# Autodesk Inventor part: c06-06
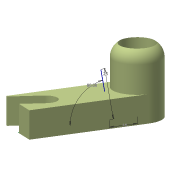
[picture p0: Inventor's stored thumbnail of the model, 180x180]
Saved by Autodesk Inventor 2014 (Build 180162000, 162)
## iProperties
Created: 2013-03
Part Number: c06-06
Material: Aluminum 6061
Document SubType Name: Modeling
Designer: Thom Tremblay
Density: 2.71 g/cm^3
Appearance: Zinc Chromate 2
Author: Thom Tremblay
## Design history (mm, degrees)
sketch "Sketch1"
  geometry: L1 (0, -12.5)-(60, -12.5); L2 (60, -12.5)-(60, 12.5); L3 (60, 12.5)-(0, 12.5); L4 (0, 12.5)-(0, -12.5); 2 further points
  constraints: 8 end point, 2 parallel, 1 coincident, 1 horizontal, 1 midpoint, 1 perpendicular
  dimensions: "d1" = 25 distance of L2.end L1.end; "d2" = 60 distance of L2.end L3.end
extrude "Base" new body sketch "Sketch1" distance "d3" = 14; taper "d4" = 0 deg
sketch "Sketch2"
  geometry: C1 r 12.5 at (0, 0); 1 further point
  constraints: 1 centre point, 1 coincident
extrude "Boss" join sketch "Sketch2" distance "d5" = 35; taper "d6" = 0 deg
sketch "Sketch3"
  geometry: L1 (-60, 12.5)-(-60, -12.5) reference; L2 (-60, -6)-(-60, 6); L3 (-43.948, 5.638)-(-60, 11.481); L4 (-48.052, -5.638)-(-60, -1.289); L5 (-60, 11.481)-(-60, -1.289); A1 r 6 centre (-46, 0) between (-43.948, 5.638) and (-48.052, -5.638); 2 further points
  constraints: 8 end point, 3 midpoint, 2 point on circle, 2 point on line, 2 tangent, 1 centre point, 1 collinear, 1 horizontal alignment, 1 parallel
  dimensions: "d8" = 12 diameter of A1; "d20" = 20 dimension on A1 L1; "d27" = 70 deg angle of L1 L3
extrude "Slot" cut sketch "Sketch3" stored distance "d9" = 24; taper "d10" = 0 deg
hole "Hole1" diameter "d13" = 11; stored, may be unused: countersink angle "d17" = 90 deg, drill point angle "d19" = 118 deg; dims "d11" = 10, "d12" = 10, "d14" = 6, "d15" = 18, "d16" = 11, "d18" = 8
fillet "Fillet1" dims "d26" = 8
node "Midplane between faces"
node "Normal to Edge at Point"
node "Offset Plane"
  node "Tangent Plane"
sketch "Sketch4"
  geometry: L1 (0, 0)-(-60, 0) reference; L2 (-14, 0)-(-18.341, 24.62)
  constraints: 2 end point, 1 point on line
  dimensions: "d21" = 25 distance of L2.start L2.end; "d22" = 80 deg angle of L1 L2; "d23" = 14 distance of L1.start L2.start
sketch "Sketch5"
  geometry: L1 (0, 0)-(-19.151, 16.07); L2 (0, 0)-(25, 0); C1 r 9 at (0, 0) reference; C2 r 5.5 at (0, 0) reference
  constraints: 4 end point, 1 equal length, 1 horizontal
  dimensions: "d24" = 25 distance of L1.start L1.end; "d25" = 140 deg angle of L2 L1
body "Solid1"
workaxis "Work Axis1"
node "Plane at Angle"
other parameters: "d28" = 30 deg, "d29" = 15
